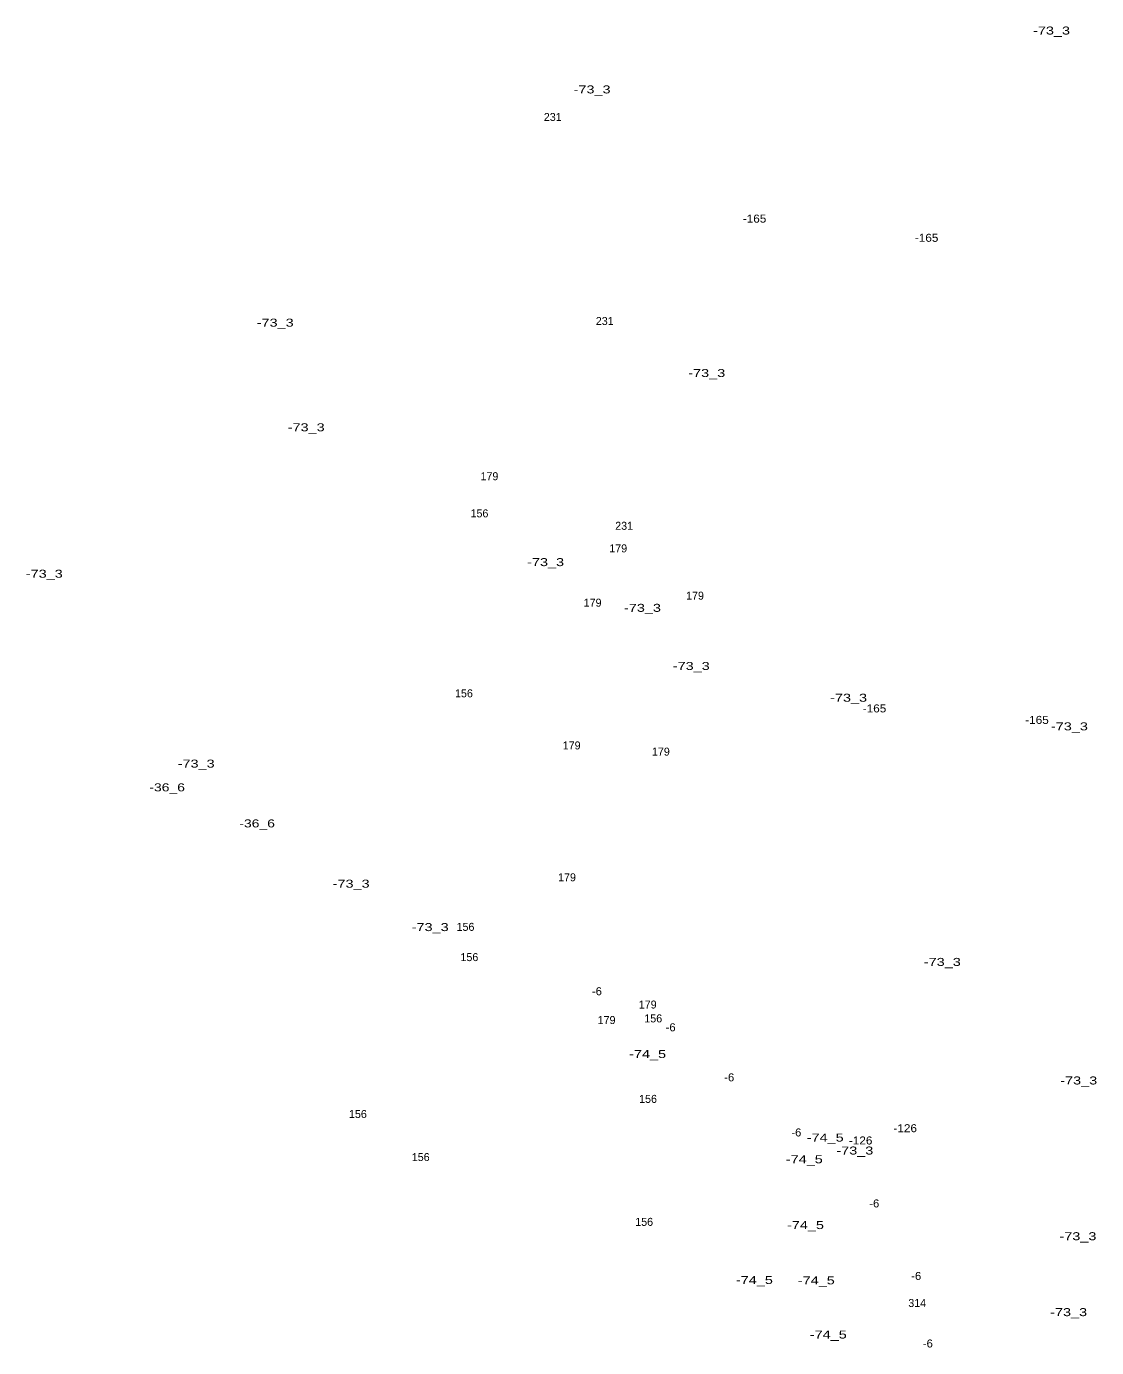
# Model space of a CAD drawing. Extents: x -658110 to -655750, y -1000429 to -997657.
# Drawn here: x -658033 to -657498, y -1000429 to -999768 of the extents above; entities that cross this region are included whole.
import ezdxf
from ezdxf.enums import TextEntityAlignment as Align

# ---------------------------------------------------------------- set-up
doc = ezdxf.new("R2010")
doc.units = 0
doc.header["$LTSCALE"] = 1.6
doc.layers.add('24', color=7, linetype='Continuous')

msp = doc.modelspace()

# ---------------------------------------------------------------- texts
at = {"layer": '24'}
for s, width, p in [('-73_3', 1.35, (-657520.32, -999772.13)), ('-73_3', 1.35, (-657749.96, -999801.57)), ('-165', 1.1, (-657668.76, -999866.17)), ('-165', 1.1, (-657582.76, -999875.75)), ('-73_3', 1.35, (-657908.35, -999918.19)), ('-73_3', 1.35, (-657692.66, -999943.37)), ('-73_3', 1.35, (-657892.86, -999970.49)), ('-73_3', 1.35, (-657773.19, -1000037.91)), ('-73_3', 1.35, (-658023.76, -1000043.71)), ('-73_3', 1.35, (-657724.78, -1000060.77)), ('-73_3', 1.35, (-657700.39, -1000089.82)), ('-73_3', 1.35, (-657621.77, -1000105.71)), ('-165', 1.1, (-657608.8, -1000111.05)), ('-165', 1.1, (-657527.59, -1000116.8)), ('-73_3', 1.35, (-657511.39, -1000120.03)), ('-73_3', 1.35, (-657947.85, -1000138.64)), ('-36_6', 1.3, (-657962.35, -1000150.51)), ('-36_6', 1.3, (-657917.37, -1000168.55)), ('-73_3', 1.35, (-657870.39, -1000198.68)), ('-73_3', 1.35, (-657830.89, -1000220.38)), ('-73_3', 1.35, (-657574.91, -1000237.8)), ('-6', 1.05, (-657747.54, -1000252.45)), ('-6', 1.05, (-657710.7, -1000270.49)), ('-74_5', 1.35, (-657722.22, -1000283.85)), ('-6', 1.05, (-657681.42, -1000295.51)), ('-73_3', 1.35, (-657506.74, -1000297.07)), ('-126', 1.1, (-657593.47, -1000320.94)), ('-6', 1.05, (-657647.87, -1000323.05)), ('-74_5', 1.35, (-657633.449, -1000325.63)), ('-126', 1.1, (-657615.74, -1000327.08)), ('-73_3', 1.35, (-657618.64, -1000332.1)), ('-74_5', 1.35, (-657643.89, -1000336.47)), ('-6', 1.05, (-657608.92, -1000358.54)), ('-74_5', 1.35, (-657643.309, -1000369.36)), ('-73_3', 1.35, (-657507.13, -1000374.94)), ('-6', 1.05, (-657587.97, -1000394.81)), ('-74_5', 1.35, (-657668.84, -1000396.83)), ('-74_5', 1.35, (-657637.89, -1000397.03)), ('-73_3', 1.35, (-657511.78, -1000412.9)), ('-74_5', 1.35, (-657631.9, -1000424.11)), ('-6', 1.05, (-657582.16, -1000428.56))]:
    msp.add_text(s, height=4, dxfattribs=dict(at, width=width)).set_placement(p, align=Align.CENTER)
for s, p in [('231', (-657769.62, -999815.34)), ('231', (-657743.64, -999917.35)), ('179', (-657801.27, -999994.96)), ('156', (-657806.25, -1000013.52)), ('231', (-657733.949, -1000019.75)), ('179', (-657736.91, -1000031.03)), ('179', (-657698.52, -1000054.69)), ('179', (-657749.7, -1000058.18)), ('156', (-657814, -1000103.51)), ('179', (-657760.17, -1000129.55)), ('179', (-657715.58, -1000132.65)), ('179', (-657762.5, -1000195.49)), ('156', (-657813.231, -1000220.26)), ('156', (-657811.291, -1000235.39)), ('179', (-657722.17, -1000259.11)), ('179', (-657742.72, -1000266.86)), ('156', (-657719.39, -1000266.03)), ('156', (-657722, -1000306.27)), ('156', (-657867.01, -1000313.83)), ('156', (-657835.611, -1000335.36)), ('156', (-657723.941, -1000367.75)), ('314', (-657587.47, -1000408.32))]:
    msp.add_text(s, height=4, dxfattribs=at).set_placement(p, align=Align.CENTER)

doc.saveas('drawing.dxf')
